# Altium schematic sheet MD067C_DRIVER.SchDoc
size 431 x 279 mm; Date: Not shown in title block; ApprovedBy: Not shown in title block; CheckedBy: Not shown in title block; Author: Not shown in title block; CompanyName: Not shown in title block; Engineer: Not shown in title block; Organization: Not shown in title block; Address1: Not shown in title block; Address2: Not shown in title block; Address3: Not shown in title block; Address4: Not shown in title block; DocumentNumber: 2; Revision: Use project parameter SCH_Rev; SheetNumber: 2; SheetTotal: 5; PageSetup: Record=PageOptions¦CenterHorizontal=True¦CenterVertical=True¦PrintScale=1.00¦XCorrection=1.00¦YCorrection=1.00¦PrintKind=0¦BorderSize=5000000¦LeftOffset=0¦BottomOffset=0¦Orientation=2¦PaperLength=1000¦PaperWidth=1000¦Scale=100¦PaperSource=15¦PrintQuality=600¦MediaType=1¦DitherType=10¦PaperKind=Letter¦PrintScaleMode=1
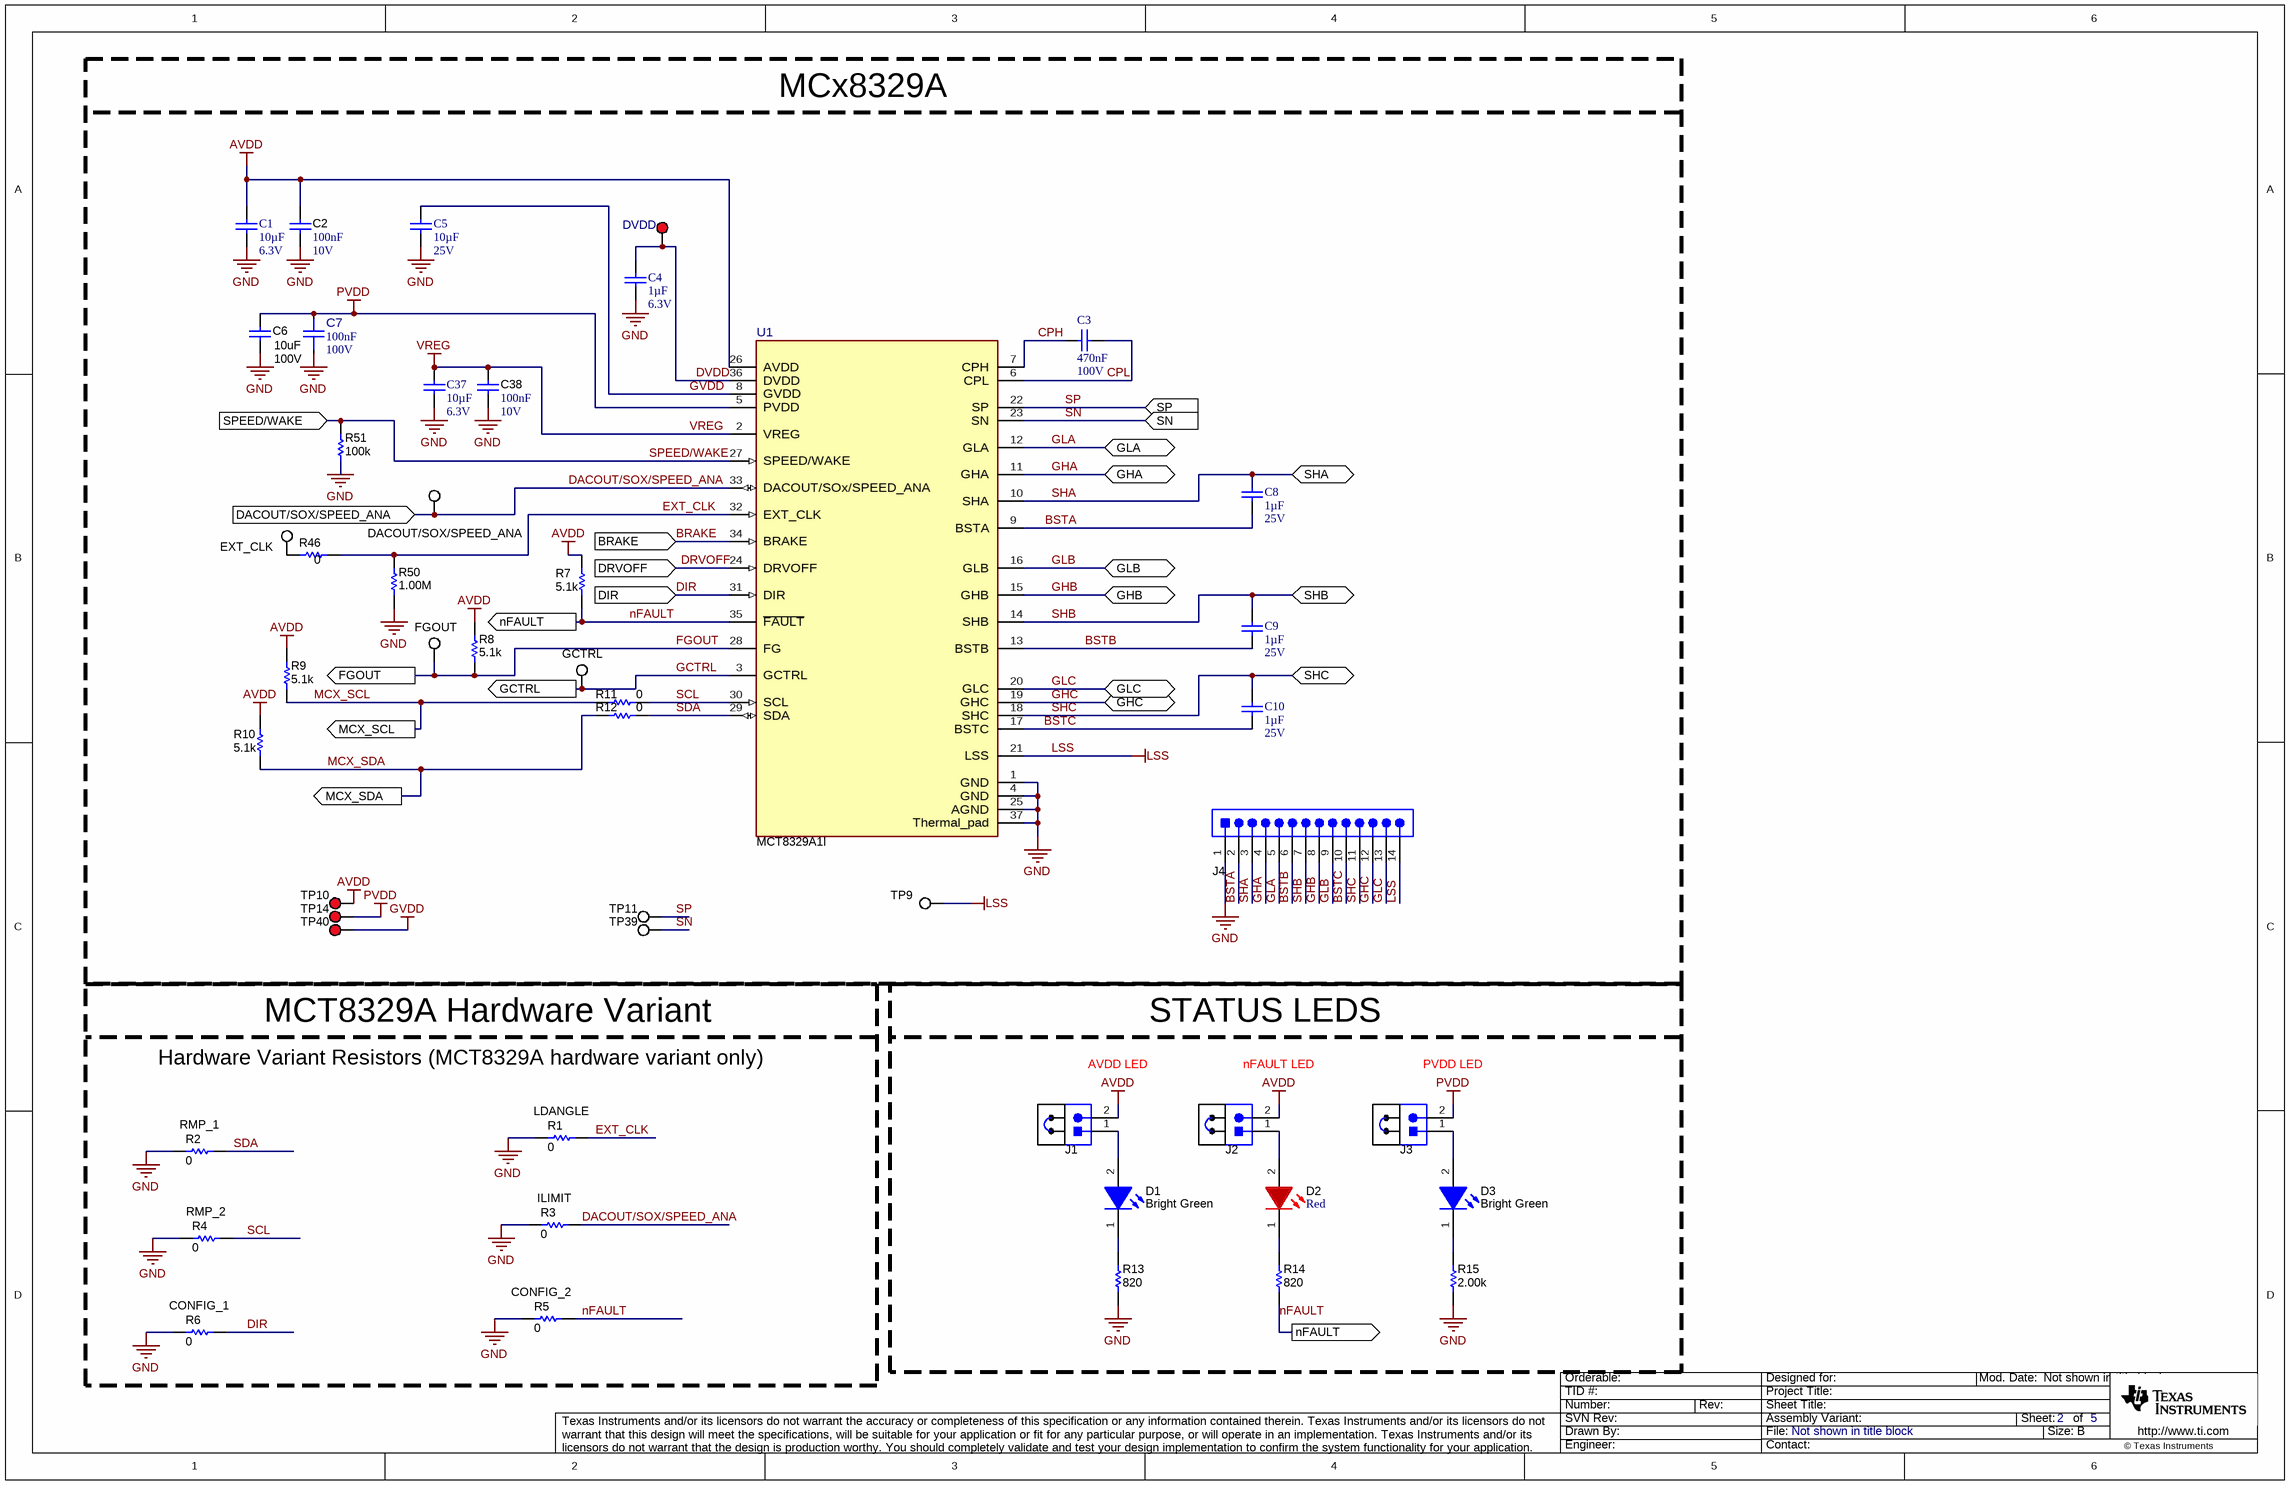
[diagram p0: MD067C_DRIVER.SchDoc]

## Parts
C1  Cap_F: 10µF  Rated Voltage (DC): 6.3V  [WCAP-CSGP_0603_L1.6W0.8H0.8_Reflow]  (hidden comment: 885012106006)
C2  Cap_F: 100nF  VDC_V: 10V  [0603]  (hidden comment: 885012206020)
C3  Cap_F: 470nF  Rated Voltage (DC): 100V  [WCAP-CSGP_0805_L2W1.25H1.25]  (hidden comment: 885012207130)
C4  Cap_F: 1µF  Rated Voltage (DC): 6.3V  [WCAP-CSGP_0603_L1.6W0.8H0.8_Reflow]  (hidden comment: 885012106003)
C5  Cap_F: 10µF  Rated Voltage (DC): 25V  [WCAP-CSGP_0603_L1.6W0.8H0.8_Reflow]  (hidden comment: 885012106031)
C6  VDC_V: 100V  ValueDisplayed: 10uF  [2220_280L]  (hidden comment: 22201C106MAT2A)
C7  Cap_F: 100nF  VDC_V: 100V  [FP-885012206120_0603-MFG]  (hidden comment: 885012206120)
C8  Cap_F: 1µF  Rated Voltage (DC): 25V  [WCAP-CSGP_0603_L1.6W0.8H0.8_Reflow]  (hidden comment: 885012106022)
C9  Cap_F: 1µF  Rated Voltage (DC): 25V  [WCAP-CSGP_0603_L1.6W0.8H0.8_Reflow]  (hidden comment: 885012106022)
C10  Cap_F: 1µF  Rated Voltage (DC): 25V  [WCAP-CSGP_0603_L1.6W0.8H0.8_Reflow]  (hidden comment: 885012106022)
C37  Cap_F: 10µF  Rated Voltage (DC): 6.3V  [WCAP-CSGP_0603_L1.6W0.8H0.8_Reflow]  (hidden comment: 885012106006)
C38  Cap_F: 100nF  VDC_V: 10V  [0603]  (hidden comment: 885012206020)
D1  value Bright Green  [WL-SMCW_Green_0805]  (hidden comment: 150080VS75000)
D2  value Red  [WL-SMCW_RED_0805]  (hidden comment: 150080RS75000)
D3  value Bright Green  [WL-SMCW_Green_0805]  (hidden comment: 150080VS75000)
J1  61300211121  [WURTH_61300211121]  (value not drawn)
J2  61300211121  [WURTH_61300211121]  (value not drawn)
J3  61300211121  [WURTH_61300211121]  (value not drawn)
J4  TSW-114-07-G-S  [TSW-114-07-G-S]  (value not drawn)
R1  ValueDisplayed: 0  [0603L]  (hidden comment: ERJ-3GEY0R00V)
R2  ValueDisplayed: 0  [0603L]  (hidden comment: ERJ-3GEY0R00V)
R3  ValueDisplayed: 0  [0603L]  (hidden comment: ERJ-3GEY0R00V)
R4  ValueDisplayed: 0  [0603L]  (hidden comment: ERJ-3GEY0R00V)
R5  ValueDisplayed: 0  [0603L]  (hidden comment: ERJ-3GEY0R00V)
R6  ValueDisplayed: 0  [0603L]  (hidden comment: ERJ-3GEY0R00V)
R7  ValueDisplayed: 5.1k  [0603L]  (hidden comment: CRCW06035K10JNEA)
R8  ValueDisplayed: 5.1k  [0603L]  (hidden comment: CRCW06035K10JNEA)
R9  ValueDisplayed: 5.1k  [0603L]  (hidden comment: CRCW06035K10JNEA)
R10  ValueDisplayed: 5.1k  [0603L]  (hidden comment: CRCW06035K10JNEA)
R11  ValueDisplayed: 0  [0603L]  (hidden comment: ERJ-3GEY0R00V)
R12  ValueDisplayed: 0  [0603L]  (hidden comment: ERJ-3GEY0R00V)
R13  ValueDisplayed: 820  [0603L]  (hidden comment: RC0603JR-07820RL)
R14  ValueDisplayed: 820  [0603L]  (hidden comment: RC0603JR-07820RL)
R15  ValueDisplayed: 2.00k  [0603L]  (hidden comment: RG1608P-202-B-T5)
R46  Res_ohm: 0  [0603]  (hidden comment: ERJ-3GEY0R00V)
R50  ValueDisplayed: 1.00M  [0603]  (hidden comment: RMCF0603FG1M00)
R51  ValueDisplayed: 100k  [0603]  (hidden comment: RT0603BRD07100KL)
SH-J1  60900213421  [Wurth_60900213421]  (value not drawn)
SH-J2  60900213421  [Wurth_60900213421]  (value not drawn)
SH-J3  60900213421  [Wurth_60900213421]  (value not drawn)
TP1  DVDD  [Keystone5000]
TP2  DACOUT/SOX/SPEED_ANA  [Keystone5002]
TP3  EXT_CLK  [Keystone5002]
TP4  FGOUT  [Keystone5002]
TP5  GCTRL  [Keystone5002]
TP9  LSS  [Testpoint_Keystone_Miniature]  (value not drawn)
TP10  AVDD  [Keystone5000]  (value not drawn)
TP11  SP  [Testpoint_Keystone_Miniature]  (value not drawn)
TP14  PVDD  [Keystone5000]  (value not drawn)
TP39  SN  [Testpoint_Keystone_Miniature]  (value not drawn)
TP40  GVDD  [Keystone5000]  (value not drawn)
U1  MCT8329A1I  [REE0036A-MFG]

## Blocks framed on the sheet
MCx8329A: C1-C10 C37 C38 J4 R7-R12 R46 R50 R51 TP1-TP5 TP9-TP11 TP14 TP39 TP40 U1
MCT8329A Hardware Variant: R1-R6
STATUS LEDS: D1-D3 J1-J3 R13-R15 SH-J1-SH-J3

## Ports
BRAKE (in), DACOUT/SOX/SPEED_ANA (in), DIR (in), DRVOFF (in), FGOUT (out), GCTRL (out), GHA (bidir), GHB (bidir), GHC (bidir), GLA (bidir), GLB (bidir), GLC (bidir), MCX_SCL (out), MCX_SDA (out), nFAULT (out), SHA (bidir), SHB (bidir), SHC (bidir), SN (in), SP (in), SPEED/WAKE (in)

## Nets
AVDD: C1.2 C2.2 J1.2 J2.2 R7.1 R8.2 R9.2 R10.2 TP10.1 U1.26(AVDD)
GND: C1.1 C2.1 C4.1 C5.1 C6.2 C7.1 C37.1 C38.2 J4.1 R1.2 R2.2 R3.2 R4.2 R5.2 R6.2 R13.1 R15.1 R50.1 R51.1 U1.1(GND) U1.4(GND) U1.25(AGND) U1.37(Thermal_pad)
GVDD: C5.2 TP40.1 U1.8(GVDD)
LSS: J4.14 TP9.1 U1.21(LSS)
PVDD: C6.1 C7.2 J3.2 TP14.1 U1.5(PVDD)
VREG: C37.2 C38.1 U1.2(VREG)
BRAKE: U1.34(BRAKE) ; port BRAKE
BSTA: C8.1 J4.2 U1.9(BSTA)
BSTB: C9.2 J4.6 U1.13(BSTB)
BSTC: C10.2 J4.10 U1.17(BSTC)
CPH: C3.2 U1.7(CPH)
CPL: C3.1 U1.6(CPL)
DACOUT/SOX/SPEED_ANA: R3.1 TP2.1 U1.33(DACOUT/SOx/SPEED_ANA) ; port DACOUT/SOX/SPEED_ANA
DIR: R6.1 U1.31(DIR) ; port DIR
DRVOFF: U1.24(DRVOFF) ; port DRVOFF
DVDD: C4.2 TP1.1 U1.36(DVDD)
EXT_CLK: R1.1 R46.2 R50.2 U1.32(EXT_CLK)
FGOUT: R8.1 TP4.1 U1.28(FG) ; port FGOUT
GCTRL: TP5.1 U1.3(GCTRL) ; port GCTRL
GHA: J4.4 U1.11(GHA) ; port GHA
GHB: J4.8 U1.15(GHB) ; port GHB
GHC: J4.12 U1.19(GHC) ; port GHC
GLA: J4.5 U1.12(GLA) ; port GLA
GLB: J4.9 U1.16(GLB) ; port GLB
GLC: J4.13 U1.20(GLC) ; port GLC
MCX_SCL: R9.1 R11.1 ; port MCX_SCL
MCX_SDA: R10.1 R12.1 ; port MCX_SDA
nFAULT: R5.1 R7.2 R14.1 U1.35(~{FAULT}) ; port nFAULT
SCL: R4.1 R11.2 U1.30(SCL)
SDA: R2.1 R12.2 U1.29(SDA)
SHA: C8.2 J4.3 U1.10(SHA) ; port SHA
SHB: C9.1 J4.7 U1.14(SHB) ; port SHB
SHC: C10.1 J4.11 U1.18(SHC) ; port SHC
SN: TP39.1 U1.23(SN) ; port SN
SP: TP11.1 U1.22(SP) ; port SP
SPEED/WAKE: R51.2 U1.27(SPEED/WAKE) ; port SPEED/WAKE
NetD1_1: D1.1(K) R13.2
NetD1_2: D1.2(A) J1.1
NetD2_1: D2.1(K) R14.2
NetD2_2: D2.2(A) J2.1
NetD3_1: D3.1(K) R15.2
NetD3_2: D3.2(A) J3.1
NetR46_1: R46.1 TP3.1

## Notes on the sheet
- Hardware Variant Resistors (MCT8329A hardware variant only)
- (near R1) LDANGLE
- AVDD LED
- nFAULT LED
- PVDD LED
- (near R2) RMP_1
- (near R4) RMP_2
- (near R3) ILIMIT
- (near R6) CONFIG_1
- (near R5) CONFIG_2

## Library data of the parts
C1 = CMP-0108062-1: WCAP-CSGP Multilayer Ceramic Chip Capacitor, General Purpose, size 0603, X5R, 10µF, 6.3VDC; Manufacturer: Wurth Elektronik; Capacitance Tolerance: +/-20%; Case/Size Code: 0603; Dissipation Factor: 10%; Insulation Resistance: 0.01GOhm; Technical Reference: X5R0603106M6R3DFCT10000; Value: 10uF
C2 C38 = CMP-0064931-4: CAP, CERM, 0.1 uF, 10 V,+/- 10%, X7R, 0603; Manufacturer: Wurth Elektronik; TaMin_C: -55°C; Polarized: N; SizeAreaWB_mm2: 4.68; Value1: Unknown; U/M: EA; Value: 0.1uF; TaMax_C: 125°C; SizeZ_mm: 1; SizeX_mm: 1.6; SizeY_mm: 0.8; SizeArea_mm2: 1.28; AEC Category: Q200
C3 = CMP-0115615-1: WCAP-CSGP Multilayer Ceramic Chip Capacitor, General Purpose, size 0805, X7R Class II, 470nF, 100VDC; Manufacturer: Wurth Elektronik; Capacitance Tolerance: +/-10%; Case/Size Code: 0805; Dissipation Factor: 10%; Insulation Resistance: 0.2GOhm; Technical Reference: X7R0805474K100DFCT10000
C4 = CMP-0111654-1: WCAP-CSGP Multilayer Ceramic Chip Capacitor, General Purpose, size 0603, X5R, 1µF, 6.3VDC; Manufacturer: Wurth Elektronik; Capacitance Tolerance: +/-20%; Case/Size Code: 0603; Dissipation Factor: 10%; Insulation Resistance: 0.1GOhm; Technical Reference: X5R0603105M6R3DFCT10000; Value: 1uF
C5 = CMP-0119169-1: WCAP-CSGP Multilayer Ceramic Chip Capacitor, General Purpose, size 0603, X5R, 10µF, 25VDC; Manufacturer: Wurth Elektronik; Capacitance Tolerance: +/20%; Case/Size Code: 0603; Dissipation Factor: 20%; Insulation Resistance: 0.01GOhm; Technical Reference: X5R0603106M025DFCT10000; Value: 10uF
C6 = CMP-0009304-2: CAP, CERM, 10 uF, 100 V, +/- 20%, X7R, 2220; Manufacturer: AVX; TaMin_C: -55°C; Polarized: N; SizeAreaWB_mm2: 53.9; Value1: Unknown; U/M: EA; Value: 10uF; TaMax_C: 125°C; SizeZ_mm: 2.8; SizeX_mm: 5.7; SizeY_mm: 5; Cap_Case: 2220; SizeArea_mm2: 28.5; Cap_F: 10µF; AEC Category: Q200
C7 = CMP-0097294-1: 0.1 µF ±10% 100V Ceramic Capacitor X7R 0603 (1608 Metric); Manufacturer: Wurth Electronics; TempCo: 15%; Value: 100nF; SizeZ_mm: 0.87mm; AEC Qualified: No
C8-C10 = CMP-0104504-1: WCAP-CSGP Multilayer Ceramic Chip Capacitor, General Purpose, size 0603, X5R, 1µF, 25VDC; Manufacturer: Wurth Elektronik; Capacitance Tolerance: +/-20%; Case/Size Code: 0603; Dissipation Factor: 10%; Insulation Resistance: 0.5GOhm; Technical Reference: X5R0603105M025DFCT10000; Value: 1uF
C37 = CMP-0108062-1: WCAP-CSGP Multilayer Ceramic Chip Capacitor, General Purpose, size 0603, X5R, 10µF, 6.3VDC; Manufacturer: Wurth Elektronik; Capacitance Tolerance: +/-20%; Case/Size Code: 0603; Dissipation Factor: 10%; Insulation Resistance: 0.01GOhm; Technical Reference: X5R0603106M6R3DFCT10000
D1 D3 = CMP-0002960-2: LED, Bright Green, SMD; Manufacturer: Wurth Elektronik; Io_A: 20mA; Value1: 0.072W; Vf_V: 2V; Type: AlInGaP; Angle: 140; Power_TotalModule: 72mW; Tjmax_C: 85°C; Vr_V: 5V; U/M: EA
D2 = CMP-0077509-2: LED, Red, SMD; Manufacturer: Wurth Elektronik; Io_A: 20mA; Value1: 0.072W; Vf_V: 2V; Type: AlInGaP; Angle: 140.0; Ir_A: 10µA; Power_TotalModule: 72mW; Vr_V: 5V
J1-J3 = CMP-0054794-2: Header, 2.54 mm, 2x1, Gold, TH; Manufacturer: Wurth Elektronik; Green_Lifecycle: Active; Pitch_mm: 2.54; Green_REACh: Passed; Row_Count: 1; Gender: Male; Shrouded: N; Cert_UL: Y
J4 = CMP-0075428-1: Header, 100mil, 14x1, Gold, TH; Manufacturer: Samtec; Voltage_V: 550V; Current_A: 6.3A; Row_Count: 1; Cert_CSA: Y; Cert_CULUS: N; CNHeader: True; CT: False; Gender: Male; Green_Lifecycle: Active; Green_REACh: Passed; Pitch_mm: 2.54
R1-R6 R11 R12 R46 = CMP-0025874-4: RES, 0, 5%, 0.1 W, AEC-Q200 Grade 0, 0603; Manufacturer: Panasonic; Power_W: 100mW; TempCo: 600 ppm/C; Value_Code: 0000; Value: 0; EIA_Code: E24; SizeX_mm: 1.6; SizeY_mm: 0.8; SizeZ_mm: 1; Value2: 0.1W; SizeArea_mm2: 1.28; AEC Qualified: Y; VDC_V: 50V; AEC Category: Q200; SizeAreaWB_mm2: 4.68
R7-R10 = CMP-0025830-4: RES, 5.1 k, 5%, 0.1 W, AEC-Q200 Grade 0, 0603; Manufacturer: Vishay-Dale; Power_W: 100mW; TempCo: 200 ppm/C; Value_Code: 5k10; Value: 5.1k; EIA_Code: E24; SizeX_mm: 1.6; SizeY_mm: 0.8; SizeZ_mm: 1; Value2: 0.1W; SizeArea_mm2: 1.28; AEC Qualified: Y; VDC_V: 75V; AEC Category: Q200; AEC Grade: 0
R13 R14 = CMP-0025941-5: RES, 820, 5%, 0.1 W, 0603; Manufacturer: Yageo; Power_W: 100mW; TempCo: 100 ppm/C; Value_Code: 820R; Value: 820; EIA_Code: E24; SizeX_mm: 1.6; SizeY_mm: 0.8; SizeZ_mm: 1; Value2: 0.1W; SizeArea_mm2: 1.28; AEC Qualified: N; VDC_V: 75V; AEC Category: Q200; SizeAreaWB_mm2: 4.68
R15 = CMP-0023463-3: RES, 2.00 k, 0.1%, 0.1 W, 0603; Manufacturer: Susumu Co Ltd; Power_W: 100mW; TempCo: 25 ppm/C; Value_Code: 2k00; U/M: EA; Value: 2.00k; EIA_Code: E192; Res_ohm: 2k; SizeX_mm: 1.6; SizeY_mm: 0.8; SizeZ_mm: 1; Value2: 0.1W; SizeArea_mm2: 1.28; VDC_V: 75V; AEC Category: Q200
R50 = CMP-0085900-1: RES, 1.00 M, 1%, 0.1 W, AEC-Q200 Grade 0, 0603; Manufacturer: Stackpole Electronics Inc; AEC Category: Q200; Res_ohm: 1M; SizeX_mm: 1.6; SizeY_mm: 0.8; Value: 1.00Meg; SizeAreaWB_mm2: 4.68; SizeArea_mm2: 1.28; Power_W: 100mW; AEC Qualified: Y; EIA_Code: E96; AEC Grade: 0; Value_Code: 1M00; Value2: 0.1W; TempCo: 100 ppm/C; SizeZ_mm: 1
R51 = CMP-0023630-1: RES, 100 k, 0.1%, 0.1 W, 0603; Manufacturer: Yageo America; Power_W: 100mW; TempCo: 25 ppm/C; U/M: EA; Value: 100k; EIA_Code: E192; SizeX_mm: 1.6; SizeY_mm: 0.8; SizeZ_mm: 1; Value2: 0.1W; SizeArea_mm2: 1.28; VDC_V: 75V; AEC Category: Q200
SH-J1-SH-J3 = CMP-0003761-2: Shunt, 2.54mm, Gold, Black; Manufacturer: Wurth Elektronik; Value: 1x2
TP1 TP10 TP14 TP40 = CMP-0055137-1: Test Point, Miniature, Red, TH; PartNumber: 5000; Manufacturer: Keystone; ContactFinish: Silver; CNHeader: FALSE; CT: TRUE; Green_Lifecycle: Active; Green_REACh: Passed
TP2-TP5 = CMP-0055139-1: Test Point, Miniature, White, TH; Manufacturer: Keystone; CNHeader: FALSE; Green_Lifecycle: Active; Green_REACh: Passed; ContactFinish: Silver; CT: TRUE
TP9 TP11 TP39 = CMP-0055152-1: Test Point, Miniature, SMT; Manufacturer: Keystone; CNHeader: FALSE; Green_Lifecycle: Active; Green_REACh: Passed; CT: TRUE
U1 = CMP-0095893-1: High Speed Sensorless Trapezoidal Control 4.5 to 60 V Three-phase BLDC Gate Driver; Manufacturer: Texas Instruments; Number Of Outputs: 3; AEC Qualified: No; Standoff Height: 0mm; Min Supply Voltage: 4.5V; Motor Type: Brushless DC; SizeZ_mm: 0.8mm; TaMin_C: -40°C; Switching Frequency: 100kHz; TJmax_C: +150°C; Max Supply Voltage: 60V; TaMax_C: +125°C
